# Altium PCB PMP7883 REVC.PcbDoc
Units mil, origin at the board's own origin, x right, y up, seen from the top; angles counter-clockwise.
Board outline 2805 x 1860 mil, 2 copper layers (Top Layer, Bottom Layer), stack 62.6 mil thick; 71 components, 35 nets, 157 pads, 20 vias.
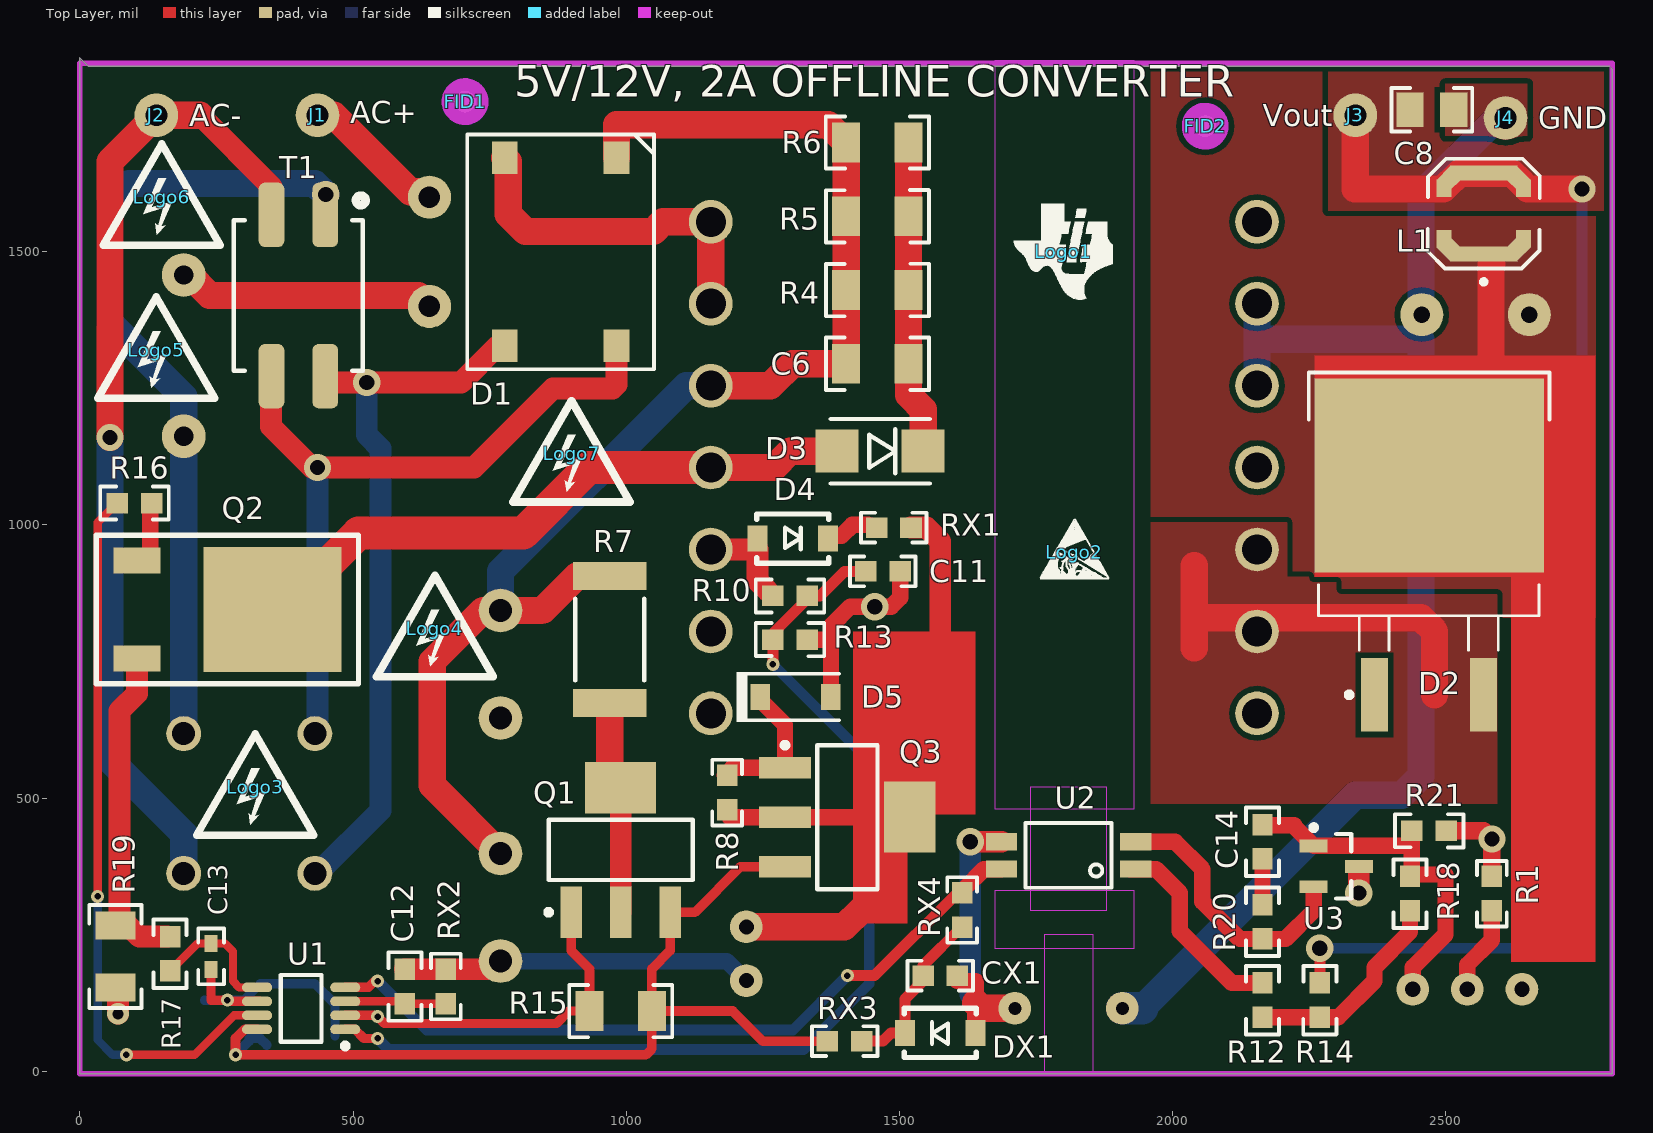
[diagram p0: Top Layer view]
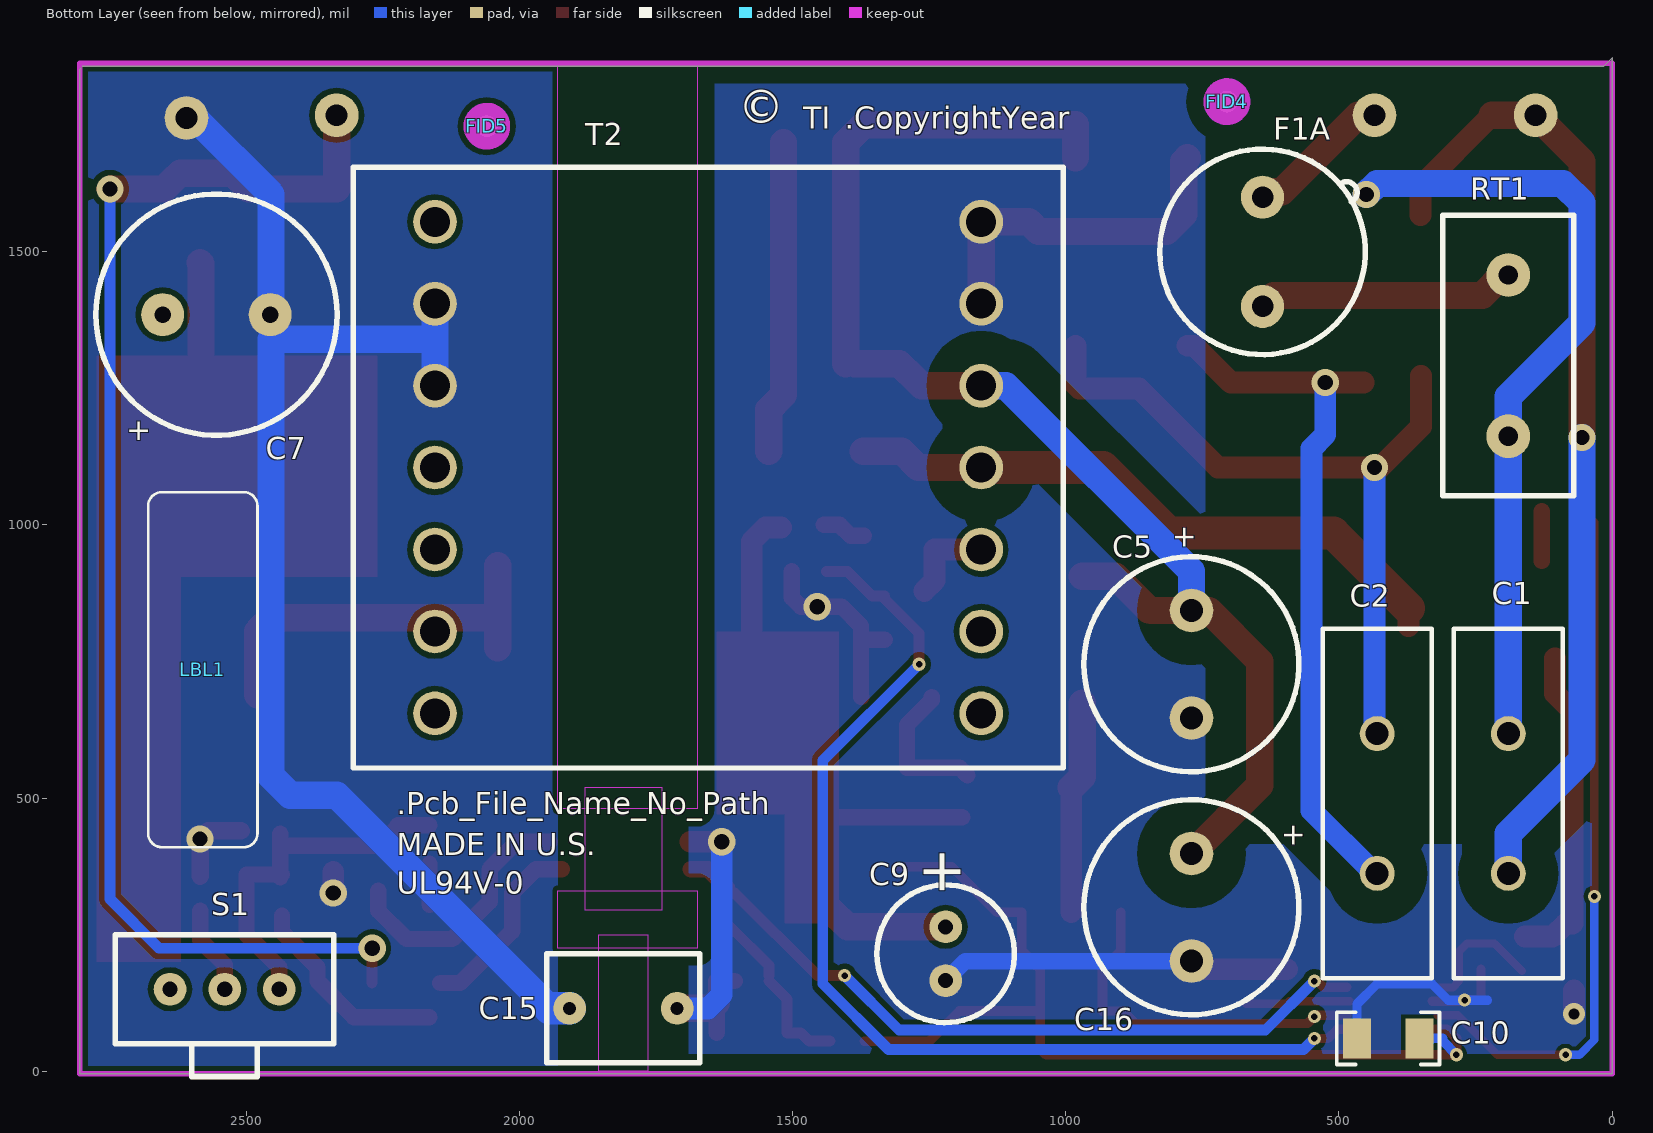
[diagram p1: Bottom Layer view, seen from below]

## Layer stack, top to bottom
Top Layer: signal copper 2.8
Dielectric: core 57, FR-4, Dk 4.8
Bottom Layer: signal copper 2.8

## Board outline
0,-5 2805,-5 2805,1835 2800,1840 15,1840 0,1855 0,-5

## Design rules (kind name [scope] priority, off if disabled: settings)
AcuteAngle [All] p1: minimum=4.50000000000000E+0001 checktracksonly=FALSE
AssemblyTestPointUsage [All] p1: valid=2
Clearance "Clearance T2_1_2" [(InPadClass('T2 Pin1_2')) vs InNet('GND')] p1: gap=10
Clearance "Clearance NetD4_2" [InNet('NetD4_2') vs InNet('GND')] p2: gap=10
Clearance "Clearance NetRX4_1" [InNet('NetRX4_1') vs InNet('GND')] p3: gap=10
Clearance "Clearance NetC11_1" [InNet('NetC11_1') vs InNet('GND')] p4: gap=10
Clearance "Clearance NetQ1_1" [InNet('NetQ1_1') vs InNet('GND')] p5: gap=10
Clearance Clearance_NetR16_1 [InNet('NetR16_1')] p6: gap=8
Clearance Clearance_NetC10_2 [InNet('NetC10_2')] p7: gap=8
Clearance Clearance_NetC9_1 [InNet('NetC9_1')] p8: gap=10
Clearance "Clearance VOUT" [InNet('VOUT')] p9: gap=10
Clearance "Clearance NetD2_3" [InNet('NetD2_3')] p10: gap=10
Clearance "Clearance SGND" [InNet('SGND')] p11: gap=10
Clearance Clearance_NetC7_1 [InNet('NetC7_1')] p12: gap=10
Clearance "Clearance_High Voltage to ALL" [(InNetClass('HIGH VOLTAGE'))] p13: gap=60
Clearance Clearance_Polygon [IsRegion] p14: gap=32
Clearance Clearance_BoardEdge_MountingHoles [OnCopper and InComponentClass('Mounting Holes') vs IsKeepOut] p15: gap=40
Clearance Clearance_BoardEdge_Poly [OnCopper and InPoly vs IsKeepOut] p16: gap=25
Clearance Clearance_BoardEdge [OnCopper and Not InComponentClass('Logo') and not InComponentClass('FiducialMark') and not InRegion(1000,500,4000,800) vs IsKeepOut] p17: gap=20
Clearance Clearance_IC [HasFootprint('MUA08A_L')] p18: gap=7
Clearance Clearance_All [All] p19: gap=8
ComponentClearance ComponentClearance_ScrewToNut [(HasFootprint('NY PMS 440 0025 PH')) vs (HasFootprint('Keystone_1902C'))] p1 off: gap=5 collisioncheckmode=3 verticalgap=10 showdistances=FALSE
ComponentClearance ComponentClearance_MountingHoles [InComponentClass('Mounting Holes')] p2 off: gap=40 collisioncheckmode=3 verticalgap=100000 showdistances=FALSE
ComponentClearance ComponentClearance_SmallPassives [HasFootprint('0201*') or HasFootprint('0402*') or HasFootprint('0508') or HasFootprint('0603*') or HasFootprint('0612') or HasFootprint('0805*') or HasFootprint('0815*') or HasFootprint('0830*') or HasFootprint('1206*') or HasFootprint('1210*') or HasFootprint('1808*') or HasFootprint('1812*') or HasFootprint('1825*') or HasFootprint('2010*') or HasFootprint('2220*') or HasFootprint('2225*') or HasFootprint('2512*') or HasFootprint('2728*') or HasFootprint('3518*') vs HasFootprint('0201*') or HasFootprint('0402*') or HasFootprint('0508') or HasFootprint('0603*') or HasFootprint('0612') or HasFootprint('0805*') or HasFootprint('0815*') or HasFootprint('0830*') or HasFootprint('1206*') or HasFootprint('1210*') or HasFootprint('1808*') or HasFootprint('1812*') or HasFootprint('1825*') or HasFootprint('2010*') or HasFootprint('2220*') or HasFootprint('2225*') or HasFootprint('2512*') or HasFootprint('2728*') or HasFootprint('3518*')] p3: gap=20 collisioncheckmode=3 verticalgap=10 showdistances=FALSE
ComponentClearance ComponentClearance_THtoSMT_TopLayer [IsThruComponent and OnLayer('Top Layer') vs IsSMTComponent and  OnLayer('Top Layer')] p4: gap=50 collisioncheckmode=3 verticalgap=100000 showdistances=FALSE
ComponentClearance ComponentClearance_THtoSMT_BotLayer [IsThruComponent and OnLayer('Bottom Layer') vs IsSMTComponent and  OnLayer('Bottom Layer')] p5: gap=50 collisioncheckmode=3 verticalgap=100000 showdistances=FALSE
ComponentClearance ComponentClearance_THtoTH [IsThruComponent vs IsThruComponent] p6: gap=50 collisioncheckmode=3 verticalgap=100000 showdistances=FALSE
ComponentClearance [All] p7: gap=50 collisioncheckmode=3 verticalgap=10 showdistances=FALSE
DiffPairsRouting [All] p1: maxlimit=100 minlimit=10 mostfreqgap=10 maxuncoupledlength=1000
FabricationTestPointUsage TestPointUsage [All] p1: valid=2 allowmultiple=FALSE
FabricationTestpoint Testpoint [All] p1: side=3 testpointundercomponent=TRUE minsize=40 maxsize=100 preferedsize=60 minholesize=0 maxholesize=40 preferedholesize=32 testpointgrid=1 allowsidetop=TRUE allowsidebottom=TRUE usegrid=TRUE gridtolerance=0.01
FanoutControl Fanout_LCC [IsLCC] p1: bgadir=Out bgaviamode=Centered fanoutstyle=Auto fanoutdirection=Alternating viagrid=1 // Fanout_LCC (Default Rule)
FanoutControl Fanout_BGA [IsBGA] p2: bgadir=Out bgaviamode=Centered fanoutstyle=Auto fanoutdirection=Alternating viagrid=1 // Fanout_BGA (Default Rule)
FanoutControl Fanout_Default [All] p4: bgadir=Out bgaviamode=Centered fanoutstyle=Auto fanoutdirection=Alternating viagrid=1 // Fanout_Default (Default Rule)
FanoutControl Fanout_Small [(CompPinCount < 5)] p5: bgadir=Out bgaviamode=Centered fanoutstyle=Auto fanoutdirection=OutThenIn viagrid=1 // Fanout_Small (Default Rule)
Height [All] p1 off: minheight=0 maxheight=1000 prefheight=500
HoleSize [All] p1: absolutevalues=TRUE maxlimit=251 minlimit=10 maxpercent=80.000 minpercent=20.000
MinimumAnnularRing [All] p1: minimumring=6
MinimumSolderMaskSliver MinimumSolderMaskSliver_Logo [InComponentClass('Logo') vs InComponentClass('Logo')] p1: minsoldermaskwidth=0.7
MinimumSolderMaskSliver [All] p2: minsoldermaskwidth=4
PlaneConnect [All] p1: planeconnectstyle=Relief reliefexpansion=10 reliefentries=4 reliefconductorwidth=10 reliefairgap=10
PolygonConnect [All] p1: connectstyle=Direct reliefconductorwidth=10 reliefentries=4 polygonreliefangle="90 Angle" airgapwidth=10
RoomDefinition "LM5023 APEC Rev 2" [InComponentClass('LM5023 APEC Rev 2')] p1 off: confinementstyle=ConfineIn formatcopy=TRUE lockcomponents=FALSE outline -692,-1534 1308,-1534 1308,-534 -692,-534
RoutingVias [All] p1: holewidth=16 width=34 viastyle="Through Hole" minholewidth=8 minwidth=26 maxholewidth=40 maxwidth=65
SMDToCorner [All] p1: distance=30000
SilkToSilkClearance [All] p1: silktosilkclearance=5
SilkscreenOverComponentPads [All] p1: minsilkscreentomaskgap=5
SolderMaskExpansion [All] p1: expansion=3
Width [All] p1: maxlimit=100 minlimit=6 preferedwidth=10 checkconnectedcopper=TRUE
13 further rules are at their usual default settings.

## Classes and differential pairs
component class "LM5023 APEC Rev 2": C1 C2 C5 C6 C7 C8 C9 C10 C11 C12 C13 C14 C15 C16 CX1 D1 D2 D3 D4 D5 DX1 F1 F1A J1 J2 J3 J4 L1 Q1 Q2 Q3 R1 R4 R5 R6 R7 R8 R10 R12 R13 R14 R15 R16 R17 R18 R19 R20 R21 RT1 RX1 RX2 RX3 RX4 S1 T1 T2 U1 U2 U3
component class FiducialMark: FID1 FID2 FID4 FID5
component class Logo: Logo1
net class "HIGH VOLTAGE": IN+ IN- NetC1_1 NetC2_1 NetC2_2 NetD3_2 NetF1A_1 VIN
component class Hardware_ANSI-B: !PCB FID1 FID2 FID4 FID5 LBL1 Logo1 Logo2 Logo3 Logo4 Logo5 Logo6 Logo7
component class Label: LBL1
pad class "T2 Pin1_2": T2-1 T2-2

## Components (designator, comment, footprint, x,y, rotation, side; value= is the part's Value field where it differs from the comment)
C1 "BC2361-ND" VY2103M63Y5US63V7 190,490 r270 bottom locked
C2 "BC2361-ND" VY2103M63Y5US63V7 430,490 r90 bottom locked
C5 "EEU-EE2W100U" EEUEE2W100U 770,745 r270 bottom
C6 "C3216C0G2J332J" 1206 1460,1295 r0 top
C7 "UHM1C152MPD" "10 X 20 HM" 2555,1385 r180 bottom
C8 "0805YD106MAT2A" 0805_HV 2475,1760 r0 top
C9 "ECA-2AM220" "PANASONIC M" 1220,215 r270 bottom
C10 "C3216X7R1E475K" 1206 410,60 r180 bottom
C11 "06035A471JAT2A" 0603 1470,915 r0 top
C12 "C1608C0G1E103J" 0603 595,155 r90 top
C13 "GRM1555C1H221JA01D" 0402 240,210 r270 top
C14 "C0603C821K5RACTU" 0603 2165,420 r270 top
C15 "DEBB33A221KC1B" "MURATA C1" 1810,115 r180 bottom
C16 "EEU-EE2W100U" EEUEE2W100U 770,300 r270 bottom
CX1 "0603YC104JAT2A" 0603 1575,175 r0 top
D1 "DF1506S" DF-S 880,1500 r270 top
D2 "8TQ100SPBF" DDPAK 2470,935 r90 top
D3 "US1J-13-F" SMA 1465,1135 r180 top
D4 "RF071M2S" SOD-123 1305,975 r180 top
D5 "MMSZ5245B-7-F" SOD-123 1310,685 r0 top
DX1 "MMSZ5229B-7-F" SOD-123 1575,70 r0 top
F1 "37002500410" 37002500410 3033,236 r0 top
F1A "56000001009" 56000001009 640,1500 r90 bottom
FID1 "Fiducial" Fiducial10-20 705,1775 r0 top
FID2 "Fiducial" Fiducial10-20 2060,1730 r0 top
FID4 "Fiducial" Fiducial10-20 705,1775 r180 bottom
FID5 "Fiducial" Fiducial10-20 2060,1730 r180 bottom
J1 "TH PAD" "TH PAD" 435,1750 r0 top
J2 "TH PAD" "TH PAD" 140,1750 r0 top
J3 "TH PAD" "TH PAD" 2335,1750 r0 top
J4 "TH PAD" "TH PAD" 2610,1745 r0 top
L1 "LPS4012-681MLB" LPS4012 2570,1570 r90 top
LBL1 "Size: 0.65\" x 0.20 \"" Label_650x200 2580,735 r270 bottom
Logo1 "Texas Instruments" TI_Symbol_Overlay_Small 1800,1500 r0 top
Logo2 "ESD Susceptible" ESD_Overlay_Small 1820,950 r0 top
Logo3 "DANGER HIGH VOLTAGE" IEC_HighVoltage_Small 321,520 r0 top
Logo4 "DANGER HIGH VOLTAGE" IEC_HighVoltage_Small 650,810 r0 top
Logo5 "DANGER HIGH VOLTAGE" IEC_HighVoltage_Small 140,1320 r0 top
Logo6 "DANGER HIGH VOLTAGE" IEC_HighVoltage_Small 150,1600 r0 top
Logo7 "DANGER HIGH VOLTAGE" IEC_HighVoltage_Small 900,1130 r0 top
Q1 "BSP135 L6433" SOT-223 990,405 r90 top
Q2 "IPD60R750E6" "PG TO252-3" 270,845 r180 top
Q3 "PZTA42,115" SOT-223 1405,465 r0 top
R1 "CRCW060311K0FKEA" 0603 2585,325 r270 top
R4 "CRCW1206249KFKEA" 1206 1460,1430 r0 top
R5 "CRCW1206249KFKEA" 1206 1460,1565 r180 top
R6 "CRCW1206249KFKEA" 1206 1460,1700 r0 top
R7 "10k" 2512 970,790 r90 top
R8 "RC0603FR-0723K7L" 0603 1185,510 r270 top
R10 "CRCW060363K4FKEA" 0603 1300,870 r180 top
R12 "CRCW06031K21FKEA" 0603 2165,130 r270 top
R13 "CRCW06032K80FKEA" 0603 1300,790 r180 top
R14 "CRCW060310R0FKEA" 0603 2270,130 r90 top
R15 "CRCW120610M0FKEA" 1206 990,110 r0 top
R16 "CRCW06034R75FKEA" 0603 100,1040 r0 top
R17 "CRCW06031K00FKEA" 0603 165,215 r90 top
R18 "CRCW060360K4FKEA" 0603 2435,325 r270 top
R19 "CSR1206FKR250" 1206 65,210 r90 top
R20 "CRCW0603604KFKEA" 0603 2165,273.5 r90 top
R21 "CRCW060320K0FKEA" 0603 2470,440 r180 top
RT1 "MF72-030D11" MF72-D11_02 190,1310 r270 bottom
RX1 "RC0603FR-0722R1L" 0603 1490,995 r180 top
RX2 "RC0603FR-07100KL" 0603 670,155 r270 top
RX3 "CRCW06031K00FKEA" 0603 1400,55 r180 top
RX4 "CRCW06031K00FKEA" 0603 1615,295 r270 top
S1 "SS12SDH2" SS12SDH2 2540,150 r180 bottom
T1 "50475C" 50475C 400,1420 r270 top
T2 "custom" 7508112324_0 1655,1105 r0 bottom locked
U1 "LM5023" MUA08A_L 405,115 r180 top
U2 "PS2811-1-M-A" PS2811-1 1810,395 r180 top
U3 "LMV431BIMF/NOPB" MF03A_N 2300,375 r0 top

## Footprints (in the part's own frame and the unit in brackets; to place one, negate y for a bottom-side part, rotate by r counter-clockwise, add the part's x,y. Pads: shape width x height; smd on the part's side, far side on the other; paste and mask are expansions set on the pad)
"10 X 20 HM" [mm] "10 X 20 RADIAL NICHICON HM"
  round 2 hole 0.762: 1(-2.5,0) 2(2.5,0)
  silkscreen extent -5.61,-5.61 5.61,5.61, body extent -5.59,-5.59 5.59,5.59, height 20
0402 [mm] "0402 from SM-752 data"
  rect 0.8x0.6 smd: 1(-0.6,0) 2(0.6,0)
  silkscreen extent -1.3,-0.6 1.3,0.6, body extent -0.55,-0.3 0.55,0.3, height 0.6
0603 [mm] "0603 from SM-752 data"
  rect 1x0.95 smd: 1(-0.8,0) 2(0.8,0)
  silkscreen extent -1.52,-0.69 1.52,0.69, body extent -0.87,-0.47 0.87,0.47, height 0.85
0805_HV [mil] "0805 with 30mil clearance between pads"
  rect 50x63 smd: 1(-40,0) 2(40,0)
  silkscreen extent -74,-40 74,40, body extent -43,-29 43,29, height 43
1206 [mm] "1206 from SM-752 data"
  rect 1.3x1.85 smd: 1(-1.45,0) 2(1.45,0)
  silkscreen extent -2.39,-1.22 2.39,1.22, body extent -1.7,-0.9 1.7,0.9, height 1.35
2512 [mm] "Chip Resistor, Body 6.3x3.2mm, IPC Medium Density"
  rect 1.3x3.4 smd: 1(-2.95,0) 2(2.95,0)
  silkscreen extent -1.9,-1.6 1.9,1.6, body extent -3.22,-1.67 3.22,1.67, height 0.71
50475C [mm] "CHOKE COMMON MODE 4.7MH 0.4A SMD"
  rrect50% 3x1.2 smd: 1(-3.75,1.25) 2(-3.75,-1.25) 3(3.75,-1.25) 4(3.75,1.25)
  silkscreen extent -4.65,-3 3.5,3.12, body extent -3.5,-3 3.5,3, height 3.8
7508112324_0 [mil] "Wurth Elektronik Transformer"
  round 60 on Bottom Overlay: 0(-700,550)
  round 80 hole 55: 1(-500,450) 2(-500,300) 3(-500,150) 4(-500,0) 5(-500,-150) 6(-500,-300) 7(-500,-450) 8(500,-450) 9(500,-300) 10(500,-150) 11(500,0) 12(500,150) 13(500,300) 14(500,450)
  silkscreen extent -650,-550 650,550, body extent -650,-550 650,550, height 900
37002500410 [mil] "FUSE FAST 250VAC 250MA RADIAL"
  body extent -166,-167 167,167, height 484
56000001009 [mm] "Fuseholders, Clips, & Hardware 6.3A/1.6W/4.3mm TR5/TE5 Holder"
  round 2 hole 1: 1(-2.54,0) 2(2.54,0)
  silkscreen extent -4.78,-4.78 4.78,4.78, body extent -4.75,-4.72 4.71,4.76, height 5.7
DDPAK [mil] "D2-PAK, 3-Pads, Body 9.7x10.4mm (max), TO-263AB, using Vishay Silionix recommended pad sizes"
  rect 135x49.49 smd: 1(-246.06,100) 3(-246.06,-100)
  rect 355x420 smd paste-181.1: 4(155.51,0)
  silkscreen extent -251,-220 344,220, body extent -295,-202 324,202, height 180
DF-S [mm] "Diodes Inc. recommended land pattern per ap02001.pdf rev 30"
  rect 1.52x1.2 smd: 1(-4.37,2.6) 2(-4.37,-2.6) 3(4.37,-2.6) 4(4.37,2.6)
  silkscreen extent -5.46,-4.34 5.46,4.34, body extent -3.34,-4.36 3.34,4.33, height 2.6
EEUEE2W100U [mil] "CAP ALUM 10UF 450V 20% RADIAL"
  round 80 hole 42: 1(-98.43,0) 2(98.43,0)
  silkscreen extent -197,-197 197,197, body extent -195,-196 200,196, height 799
ESD_Overlay_Small [mil]
  silkscreen extent -62,-48 64,61
Fiducial10-20 [mm]
  round 1 smd paste-0.5 mask+0.5: 1(0,0)
  Keep-Out Layer circle w1.178: c0,0 r0.5
IEC_HighVoltage_Small [mil]
  silkscreen extent -107,-88 107,97
Label_650x200 [mil] "Thermal Transfer Label"
  silkscreen extent -325,-100 325,100, body extent -326,-101 326,101, height 1
LPS4012 [mm] "Coilcraft recommended land pattern.  Document 433-2, rev 10/20/08"
  rect 0.7x3.124 smd: 1(-1.881,0) 2(1.881,0)
  rect 0.902x0.801 smd rot 45: 1(-1.592,1.605) 2(1.592,-1.605)
  rect 0.902x0.801 smd rot 135: 1(-1.592,-1.605) 2(1.592,1.605)
  rect 0.812x0.7 smd: 1(-1.168,1.85) 1(-1.168,-1.85) 2(1.168,1.85) 2(1.168,-1.85)
  silkscreen extent -3.26,-2.6 2.55,2.6, body extent -2.05,-2.05 2.05,2.05, height 1.22
MF03A_N [mm] "SOT23, 3-Leads, Body 2.9x1.3mm, Pitch 0.95mm, Lead Span 2.4mm, IPC Medium Density"
  rect 1.3x0.6 smd: 1(-1.05,0.95) 2(-1.05,-0.95) 3(1.05,0)
  silkscreen extent -1.17,-1.5 0.7,1.92, body extent -0.7,-1.5 0.7,1.5, height 1.12
MF72-D11_02 [mil] "Cantherm Current Limiter MF72-D11_02 Type"
  round 80 hole 35: 1(-147.64,0) 2(147.64,0)
  silkscreen extent -257,-120 257,120, body extent -260,-120 260,120, height 520
MUA08A_L [mm] "TSOP, 8-Leads, Body 3x3mm, Pitch 0.65mm, IPC High Density"
  oval 1.4x0.45 smd: 1(-2.05,0.975) 2(-2.05,0.325) 3(-2.05,-0.325) 4(-2.05,-0.975) 5(2.05,-0.975) 6(2.05,-0.325) 7(2.05,0.325) 8(2.05,0.975)
  silkscreen extent -2.17,-1.55 0.95,1.87, body extent -1.6,-1.6 1.6,1.6, height 1.09
"MURATA C1" [mil] "MURATA DEBB C1"
  round 60 hole 23.62: 1(-98.43,0) 2(98.43,0)
  silkscreen extent -140,-100 140,100, body extent -140,-100 140,100, height 591
"PANASONIC M" [mil] "PANASONIC M TYPE ALUMINUM CAPACITOR"
  round 60 hole 27.56: 1(-49.21,0) 2(49.21,0)
  silkscreen extent -126,-126 126,126, body extent -125,-125 125,125, height 441
"PG TO252-3" [mm] "TO252-3 INFINEON TECHNOLOGIES"
  rect 2.2x1.2 smd: 1(4.2,-2.28) 3(4.2,2.28)
  rect 6.4x5.8 smd: 2(-2.1,0)
  silkscreen extent -6.1,-3.45 6.1,3.45, body extent -6.07,-3.5 6.07,3.47, height 2.41
PS2811-1 [mm] "NEC optocoupler"
  rect 1.45x0.8 smd: 1(-3.125,0.635) 2(-3.125,-0.635) 3(3.125,-0.635) 4(3.125,0.635)
  silkscreen extent -2,-1.5 2,1.5, body extent -2.2,-1.5 2.2,1.5, height 2.1
SMA [mm] "Molded Diode, 2-Leads, Body 4.3x2.6mm, IPC Medium Density, based on OnSemi component dimensions and land pattern"
  rect 2x2 smd: 1(-2,0) 2(2,0)
  silkscreen extent -2.3,-1.5 2.3,1.5, body extent -2.28,-1.46 2.29,1.46, height 2.27
SOD-123 [mm] "On Semi recommended land pattern"
  rect 0.915x1.22 smd: 1(-1.637,0) 2(1.637,0)
  silkscreen extent -1.68,-1.14 1.68,1.14, body extent -1.42,-0.9 1.42,0.9, height 1.35
SOT-223 [mm] "SOT223/SC73, 4-Leads, Body 6.5x3.5mm, Pitch 2.3mm, Lead Span 7mm, IPC Medium Density"
  rect 2.4x1 smd: 1(-2.9,2.3) 2(-2.9,0) 3(-2.9,-2.3)
  rect 2.4x3.3 smd: 4(2.9,0)
  silkscreen extent -3.02,-3.35 1.4,3.47, body extent -1.85,-3.35 1.85,3.35, height 1.8
SS12SDH2 [mil] "NKK SERIES SS SWITCH"
  round 60 hole 28: 1(-100,0) 2(0,0) 3(100,0)
  silkscreen extent -200,-160 200,100, body extent -200,-160 200,100, height 150
"TH PAD" [mil] "THROUGH HOLE PAD"
  round 80 hole 40: 1(0,0)
TI_Symbol_Overlay_Small [mil]
  silkscreen extent -90,-88 91,88
VY2103M63Y5US63V7 [mil] "CAP CER 10000PF 300V 20% RADIAL"
  round 64 hole 42: 1(-127.95,0) 2(127.95,0)
  silkscreen extent -320,-100 320,100, body extent -314,-99 314,98, height 785

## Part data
C1 C2: library part VY2103M63Y5US63V7, "CAP CER 10000PF 300V 20% RADIAL"
C5 C16: library part EEUEE2W100U, "CAP ALUM 10UF 450V 20% RADIAL"
C6: "CAP, CERM, 3300pF, 630V, +/-5%, C0G/NP0, 1206"
C7: library part Capacitor_Polarized, "CAP, [CAP ALUM 1500UF 16V 20% RADIAL"
C8: "CAP, CERM, 10uF, 16V, +/-20%, X5R, 0805"
C9: "CAP ALUM 22UF 100V 20% RADIAL"
C10: "CAP, CERM, 4.7uF, 25V, +/-10%, X7R, 1206"
C11: "CAP, CERM, 470pF, 50V, +/-5%, C0G/NP0, 0603"
C12: "CAP, CERM, 0.01uF, 25V, +/-5%, C0G/NP0, 0603"
C13: "CAP, CERM, 220pF, 50V, +/-5%, C0G/NP0, 0402"
C14: "CAP, CERM, 820pF, 50V, +/-10%, X7R, 0603"
C15: "CAP CER 220PF 1KV 10% RADIAL"
CX1: "CAP, CERM, 0.1uF, 16V, +/-5%, X7R, 0603"
D1: "Diode, Switching-Bridge, 600V, 1.5A, DF-S"
D2: "DIODE SCHOTTKY 100V 8A D2PAK"
D3: library part SS14-E3/61T, "Diode, Schottky, 600V, 1A, SMA"
D4: "Diode, Ultrafast, 200V, 1A, SOD-123"
D5: "Diode, Zener, 15V, 500mW, SOD-123"
DX1: "Diode, Zener, 4.3V, 500mW, SOD-123"
F1: "FUSE FAST 250VAC 250MA RADIAL"
F1A: "Fuseholders, Clips, & Hardware 6.3A/1.6W/4.3mm TR5/TE5 Holder"
FID1 FID2 FID4 FID5: "Fiducial mark.  There is nothing to buy or mount."
J1 J2 J3 J4: "THROUGH HOLE PAD"
L1: "Inductor, Shielded Drum Core, Ferrite, 680nH, 2.4A, 0.05 ohm, SMD"
LBL1: library part THT-14-423-10, "Thermal Transfer Printable Labels, 0.650\" W x 0.200\" H - 10,000 per roll"
Logo1: library part TI_Logo, "Texas Instrument Corporate Signature"
Logo2: library part ESD_Susceptible, "ESD Susceptible Symbol"
Logo3 Logo4 Logo5 Logo6 Logo7: library part IEC_HighVoltage, "IEC 61010-1 High Voltage Warning"
Q1: library part BSP135, "MOSFET N-CH 600V 120MA SOT-223"
Q2: "MOSFET N-CH 600V 5.7A TO252-3"
Q3: library part PZTA42, "TRANS NPN 300V 100MA SOT223"
R1: "RES, 11.0k ohm, 1%, 0.1W, 0603"
R4 R5 R6: "RES, 249k ohm, 1%, 0.25W, 1206"
R7: library part CRCW251210K0FKEGHP, "RES 10.0K OHM 1W 1% 2512 SMD"
R8: library part Resistor, "RES 23.7K OHM 1/10W 1% 0603 SMD"
R10: "RES, 63.4k ohm, 1%, 0.1W, 0603"
R12: "RES, 1.21k ohm, 1%, 0.1W, 0603"
R13: "RES, 2.80k ohm, 1%, 0.1W, 0603"
R14: "RES, 10.0 ohm, 1%, 0.1W, 0603"
R15: "RES, 10.0Meg ohm, 1%, 0.25W, 1206"
R16: "RES, 4.75 ohm, 1%, 0.1W, 0603"
R17 RX3 RX4: "RES, 1.00k ohm, 1%, 0.1W, 0603"
R18: "RES, 60.4k ohm, 1%, 0.1W, 0603"
R19: "RES, 0.25 ohm, 1%, 0.5W, 1206"
R20: "RES, 604k ohm, 1%, 0.1W, 0603"
R21: "RES, 20.0k ohm, 1%, 0.1W, 0603"
RT1: "CURRENT LIMITER INRUSH 30OHM 20%"
RX1: "RES, 22.1 ohm, 1%, 0.1W, 0603"
RX2: "RES, 100k ohm, 1%, 0.1W, 0603"
S1: "SW SLIDE ULTR MINI SPDT SIDE ACT"
T1: "CHOKE COMMON MODE 4.7MH 0.4A SMD"
T2: library part 7508112324_0, "Werth Elektronik Transformer"
U1: "IC, CTLR, AC-DC Quasi Resonant PWM"
U2: "Low Input Current, Hight CTR Photocoupler"
U3: library part LMV431BIMF, "IC VREF SHUNT PREC ADJ SOT-23-3"

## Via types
v1: diameter 50, hole 28, Top Layer to Bottom Layer, 10 vias
v2: diameter 24, hole 12, Top Layer to Bottom Layer, 9 vias
v3: diameter 40, hole 20, Top Layer to Bottom Layer, 1 vias

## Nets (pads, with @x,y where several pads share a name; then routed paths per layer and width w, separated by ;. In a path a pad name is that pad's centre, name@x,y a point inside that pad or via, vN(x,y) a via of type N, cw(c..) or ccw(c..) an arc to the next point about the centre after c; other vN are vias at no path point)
GND: C5.2 C9.2 C10.1 C11.2 C12.2 C13.2 C15.2 C16.2 CX1.2 D1.2 D5.2 DX1.2 R13.1 R19.1 RX2.1 T2.6 T2.7 U1.6 U2.3 | length 2777.2
  Top Layer w17: C13.2 240,130 v2(270,130) ; v2@272.2,127.8 U1.6@329.29,127.8
  Top Layer w30: R13.1 1375,790 ; D5.2 1375,685.53 1375,790 ; C11.2 1501.5,866.5 1485,850 1410,850 1375,815 1375,790 ; CX1.2@1606.5,165 1640,165 1640,125 ; DX1.2 1639.47,119.47
  Top Layer w40: v3(70,105) R19.1@70,147.91 ; C12.2 744.92,186.5 C16.2@760,201.57 ; v1(1630,420) U2.3
  Top Layer w50: D1.2 784.37,1665.31 784.37,1568.63 815.87,1537.13 1049.48,1537.13 1067.35,1555 T2.7@1130,1555 ; T2.6 T2.7 ; 1640,125 1650,115 C15.2
  Bottom Layer w17: 228,130 v2(270,130) 300,130 330,160 430,160 467.09,122.91 C10.1@467.09,65
  Bottom Layer w30: C16.2@760,201.57 1184.21,201.57 C9.2
  Bottom Layer w40: v1(1630,420) 1630,140 1655,115 C15.2
  other v1: 1455,850
IN+: F1A.2 J1.1 | length 263
  Top Layer w50: J1.1 465,1750 605,1610 F1A.2@640,1610
IN-: C1.2 J2.1 T1.2 | length 1790.6
  Top Layer w40: 220,1750 350.79,1619.21 T1.2
  Top Layer w50: v1(55,1160) 55,1555 ; 55,1560 55,1665 J2.1 220,1750
  Bottom Layer w50: v1(55,1160) 55,570 190,435 C1.2
NetC1_1: C1.1 RT1.2 T1.1 | length 1445.7
  Bottom Layer w50: C1.1 RT1.2 190,1235 55,1370 55,1590 90,1625 430,1625 v1(450,1605)
NetC2_1: C2.1 D1.3 T1.4 | length 1307.6
  Top Layer w40: T1.4@454.52,1260.63 697.73,1260.63 765.05,1327.95 D1.3
  Bottom Layer w40: C2.1@435,362.05 550,477.05 550,1140 525,1165 v1(525,1260.63)
NetC2_2: C2.2 D1.4 T1.3 | length 1376.5
  Top Layer w40: T1.3@350,1272.36 350,1180 425,1105 721.37,1105 866.37,1250 975,1250 982.36,1257.36 D1.4
  Bottom Layer w40: C2.2@435,617.95 v1(435,1105)
NetC6_2: C6.2 D3.1 R4.2 R5.1 R6.2 | length 576
  Top Layer w50: R6.2 R5.1 R4.2 C6.2 1517.09,1237.91 1543.74,1211.26 D3.1
NetC7_1: C7.1 D2.4 L1.1 | length 265.4
  Top Layer w50: 2585,1480 2583.43,1478.43 2583.43,1385 2583.43,1231.57 D2.4@2595,1220
NetC9_1: C9.1 Q3.2 Q3.4 R8.2 RX1.1 | length 875.1
  Top Layer w30: R8.2@1190,465 1444.17,465 1521.5,542.32
  Top Layer w40: RX1.1 1550,995 1575,970 1575,745
  Top Layer w50: C9.1 1399.21,264.21 1430,295
NetC10_2: C10.2 Q1.3 Q3.3 R15.2 RX3.2 U1.8 | length 1792.8
  Top Layer w17.72: U1.8 301.61,76.61 285,60 v2(285,30) 1036.14,30 1047.09,40.94 R15.2 ; Q3.3@1310.55,374.45 Q3.3 1209.45,374.45 1125.83,290.83 Q1.3 1080.55,220.55 1047.09,187.09 R15.2 ; RX3.2 1250,55 1195,110 R15.2
  Bottom Layer w17.72: v2(285,30) 310,55 310,60 330,60 C10.2@342.09,47.91
NetC11_1: C11.1 R10.1 R13.2 U1.1 | length 1957.5
  Top Layer w17: U1.1 503.39,76.61 520,60 v2(545,60)
  Top Layer w20: v2@1268.5,746.5 R13.2 1268.5,801.39 1331.5,864.39 R10.1 1355,870 1400,915 C11.1
  Bottom Layer w20: v2(545,60) 565,40 1325,40 1445,160 1445,568.5 v2(1268.5,745)
NetC12_1: C12.1 RX2.2 U1.3 | length 191.2
  Top Layer w16: U1.3@480.71,127.8 U1.3 485.91,128 551.6,128 551.8,127.8 590.71,127.8 C12.1 RX2.2
NetC13_1: C13.1 R17.1 U1.5 | length 245.1
  Top Layer w15: R17.1 215.12,233.62 C13.1 265.69,233.62 280,219.31 280,165 291.61,153.39 U1.5
NetC14_1: C14.1 R18.1 R21.2 S1.3 U3.1 | length 670.1
  Top Layer w30: C14.1@2165,450 2223.03,450 2223.03,448.03 U3.1 2438.5,412.4 ; R18.1@2435,360 2500,360 2500,250 2440,190 S1.3 ; R18.1@2438.5,355 R21.2@2438.5,435
NetC14_2: C14.2 R20.2 | length 75
  Top Layer w30: R20.2 C14.2@2165,380
NetCX1_1: CX1.1 DX1.1 RX3.1 RX4.2 | length 312.9
  Top Layer w20: RX3.1 1470,55 1485,70 DX1.1 1510.53,132.03 CX1.1@1543.5,165 ; CX1.1 1543.5,193.5 1613.5,263.5 RX4.2
NetD2_3: D2.3 T2.12 T2.13 | length 716.4
  Top Layer w50: 2040,775 2040,830 ; 2040,925 2040,830 ; 2480,688.94 2480,805 2455,830 2040,830
NetD3_2: D3.2 Q2.2 T2.4 | length 1125.3
  Top Layer w40: Q2.2@372.68,815 Q2.2@372.68,847.68
  Top Layer w50: T2.4 1270,1105 1300,1135 D3.2@1371.26,1135
  Top Layer w60: Q2.2@372.68,847.68 510,985 811.78,985 931.78,1105 T2.4@1130,1105
NetD4_1: D4.1 RX1.2 | length 82.3
  Top Layer w30: D4.1@1369.47,980 1394.22,980 1414.22,1000 RX1.2@1443.5,1000
NetD4_2: D4.2 R10.2 T2.3 | length 169
  Top Layer w40: T2.3 1240.53,955 1240.53,897.97 R10.2@1259.25,879.25
NetD5_1: D5.1 Q3.1 R8.1 | length 264.9
  Top Layer w30: R8.1@1180,541.5 1194.06,555.55 Q3.1 1290.83,634.17 1245.53,679.47 D5.1
NetF1A_1: F1A.1 RT1.1 | length 463.9
  Top Layer w50: RT1.1@200,1457.64 237.64,1420 620,1420 F1A.1
NetQ1_1: Q1.1 R15.1 U1.2 | length 649.3
  Top Layer w17: U1.2 v2@537.8,102.2 ; v2(545,100) 557.68,87.32 872.32,87.32 895,110 R15.1
  Top Layer w17.72: Q1.1 899.45,220.55 932.91,187.09 R15.1
NetQ1_2: Q1.2 Q1.4 R7.1 | length 391.3
  Top Layer w40: Q1.2 Q1.4
  Top Layer w50: R7.1 970,539.17 Q1.4
NetQ2_1: Q2.1 R16.2 | length 91
  Top Layer w30: Q2.1@128.5,934 R16.2@128.5,1025
NetQ2_3: Q2.3 R17.2 R19.2 | length 595.8
  Top Layer w40: Q2.3 104.65,691.65 72.5,659.5 72.5,270 85,270 108.5,246.5 R17.2@160,246.5
NetR1_2: R1.2 S1.2 | length 162.1
  Top Layer w30: S1.2 2540,195 2585,240 R1.2
NetR12_1: R12.1 U2.1 | length 349.3
  Top Layer w30: U2.1@1923.03,370 1970,370 2013.75,326.25 2013.75,256.25 2108.5,161.5 2145,161.5
NetR12_2: R12.2 R14.1 R18.2 | length 379.5
  Top Layer w30: R12.2 R14.1 2303.5,98.5 2370,165 2370,190 2435,255 R18.2@2435,285
NetR16_1: R16.1 U1.7 | length 1325.7
  Top Layer w15: v2(32.5,320) 32.5,1004.5 R16.1@68.25,1040.25 ; v2(85,30) 210,30 282.2,102.2 U1.7@319.29,102.2
  Bottom Layer w15: v2(32.5,320) 32.5,57.5 60,30 v2(85,30)
NetR20_1: R20.1 U2.2 U3.2 | length 480.3
  Top Layer w30: U2.2@1945,420 2005,420 2055,370 2055,310 2122.99,242.01 R20.1 2207.01,242.01 2258.66,293.66 U3.2@2258.66,330
NetRX4_1: RX4.1 U1.4 U2.4 | length 1343.5
  Top Layer w17: U1.4 528.39,153.39 v2@540,165
  Top Layer w20: v2(1405,175) 1455,175 RX4.1@1606.5,326.5
  Top Layer w30: RX4.1@1620,335 1655,370 U2.4
  Bottom Layer w20: v2(545,165) 635,75 1305,75 v2(1405,175)
SGND: C7.2 C8.2 C15.1 J4.1 R1.1 R21.1 T2.9 T2.10 U3.3 | length 2594
  Top Layer w32: R21.1@2510,440 2570,440 v1(2585,425) R1.1
  Top Layer w40: v1(2341.34,326.34) U3.3@2341.34,365
  Bottom Layer w50: 1945,115 2335,505 2420,505 2455,540 2455,1340 2155,1340 ; T2.10 2155,1340 ; T2.9 2155,1340 ; C7.2@2455,1385 2455,1605 2595,1745 J4.1
  Bottom Layer w60: C15.1 1945,115
VIN: C5.1 C6.1 C16.1 D1.1 R4.1 R5.2 R6.1 R7.2 T2.5 | length 2521.4
  Top Layer w50: C16.1 645,523.43 645,750 738.43,843.43 C5.1 843.43,843.43 845,845 848.55,845 909.69,906.14 R7.2 ; D1.1 982.36,1732.64 1370.28,1732.64 R6.1 R5.2 R4.1 C6.1 ; T2.5 1264.03,1255 1288.4,1279.37 1289.37,1279.37 1305,1295 C6.1@1386.5,1295
  Bottom Layer w50: C5.1@778.21,843.43 C5.1 770,915 1110,1255 T2.5@1130,1255
VOUT: C8.1 J3.1 L1.2 R14.2 | length 2454.9
  Top Layer w20: R14.2 v1(2270,225)
  Top Layer w50: J3.1 2335,1615 2496.17,1615 2497.17,1616 2525.22,1644.06 2570,1644.06 2621.79,1644.06 2633.18,1632.67 2650.84,1615 v1(2750,1615)
  Bottom Layer w20: v1(2270,225) 2660,225 2750,315 v1(2750,1615)
pads on no net: D2.1 FID1.1 FID2.1 FID4.1 FID5.1 S1.1 T2.0 T2.1 T2.2 T2.8 T2.11 T2.14

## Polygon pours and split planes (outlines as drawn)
SGND on Bottom Layer "Bottom Layer-SGND " (solid, remove dead copper, pour order 9): 2805,1845 1930,1845 1930,-5 2805,-5
GND on Bottom Layer "Bottom Layer-GND" (solid, remove dead copper, pour order 14): 745,1845 1690,1845 1690,-10 745,-10 0,-5 0,985 160,985 165,415 745,415
SGND on Top Layer "Top Layer-SGND" (solid, remove dead copper, pour order 13): 2650,1845 2650,1700 2500,1700 2500,1845
NetD2_3 on Top Layer "Top Layer-NetD2_3" (solid, pour order 11): 1960,1005 1960,490 2595,490 2595,905 2210,905 2210,1005
VOUT on Top Layer "Top Layer-VOUT" (solid, remove dead copper, pour order 15): 2805,1575 2805,1845 2285,1845 2285,1575
NetC7_1 on Top Layer "Top Layer-Net C7_1" (solid, remove dead copper, pour order 12): 1960,1005 2220,1005 2220,830 2775,830 2775,1565 2280,1565 2280,1845 1960,1845

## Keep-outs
Keep-Out Layer:
  rectangle: 1765,0 1855,250
  rectangle: 1740,295 1880,520
  rectangle: 1675,225 1930,330
  rectangle: 1675,480 1930,1850
  lines w10: 0,-5 2805,-5 2805,1845 0,1845 0,0
  text ".Layer_Name" at 577,-858.49 h40
  text "880" at 3117.5,-858.49 h40

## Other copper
Top Layer:
  rectangle net NetC9_1: 1415,270 1515,470
  rectangle net NetC9_1: 1415,470 1640,805
  rectangle net NetC7_1: 2260,905 2775,1310
  rectangle net NetC7_1: 2620,200 2775,940
  text ".Layer_Name" at 577,-858.49 h40
  text "880" at 3117.5,-858.49 h40
Bottom Layer:
  text ".Layer_Name" at 577,-858.49 h40
  text "880" at 3117.5,-858.49 h40

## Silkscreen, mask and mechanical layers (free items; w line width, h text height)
Top Overlay:
  text "5V/12V, 2A OFFLINE CONVERTER" at 795,1765 h100
  text "AC+" at 495,1735 h40
  text "AC-" at 200,1730 h40
  text "Vout" at 2165,1730 h40
  text "GND" at 2670,1725 h40
  text ".Layer_Name" at 577,-858.49 h40
  text "880" at 3117.5,-858.49 h40
Bottom Overlay:
  text ".CopyrightYear" at 1405,1725 h40
  text "TI" at 1481,1725 h40
  text "©" at 1600,1715 h105
  text ".Pcb_File_Name_No_Path" at 2225,470 h40
  text "MADE IN U.S." at 2225,395 h40
  text "UL94V-0" at 2225,325 h40
  text ".Layer_Name" at 577,-858.49 h40
  text "880" at 3117.5,-858.49 h40
Top Paste:
  text ".Layer_Name" at 577,-858.49 h40
  text "881" at 3117.5,-858.49 h40
Bottom Paste:
  text ".Layer_Name" at 577,-858.49 h40
  text "881" at 3117.5,-858.49 h40
Top Solder:
  text "TI" at 870,70 h40
  text ".Layer_Name" at 577,-858.49 h40
  text ".Layer_Name" at 577,-858.49 h40
  text "880" at 3117.5,-858.49 h40
Bottom Solder:
  text ".Layer_Name" at 577,-858.49 h40
  text "880" at 3117.5,-858.49 h40
Drill Guide:
  text ".Layer_Name" at 577,-858.49 h40
  text "880" at 3117.5,-858.49 h40
M1 Board Outline:
  lines w5: 0,0 0,1840 2800,1840 2800,0 0,0
  text ".Layer_Name" at 577,-858.49 h40
  text "880" at 3117.5,-858.49 h40
M2 Board Dimensions:
  rectangle: -0.5,-285.5 124.5,-160.5
  rectangle: 124.5,-410.5 499.5,-285.5
  lines w7: -0.5,-285.5 999.5,-285.5 ; 124.5,-410.5 124.5,-160.5 ; 249.5,-410.5 249.5,-160.5 ; 499.5,-410.5 499.5,-160.5 ; 749.5,-410.5 749.5,-160.5 ; -0.5,-410.5 999.5,-410.5 999.5,-160.5 -0.5,-160.5 -0.5,-410.5
  lines w10: -0.5,-475.5 -0.5,-455.5 ; 59.5,-485.5 -0.5,-465.5 ; 59.5,-445.5 -0.5,-465.5 ; 223.58,-465.5 -0.5,-465.5 ; 775.42,-465.5 999.5,-465.5 ; 939.5,-485.5 999.5,-465.5 ; 939.5,-445.5 999.5,-465.5 ; 999.5,-475.5 999.5,-455.5
  text "1000 (mil)" at 233.58,-501.49 h60
  text ".Layer_Name" at 577,-858.49 h40
  text "880" at 3117.5,-858.49 h40
M3 3D STEP Top:
  text ".Layer_Name" at 577,-858.49 h40
  text "880" at 3117.5,-858.49 h40
M4 3D STEP Bottom:
  text ".Layer_Name" at 577,-858.49 h40
  text "880" at 3117.5,-858.49 h40
M5 Assembly Top:
  lines w7: -292,-930.17 6308,-930.17 ; -292,-726.83 6310,-726.83 ; -292,-523.5 -292,-1133.5 3713,-1133.5 6310,-1133.5 6310,-523.5 -291.5,-523.5 -291.5,-1133.5 1284,-1133.5 ; 2173,-929 2173,-523.5 ; 3926,-1133 3926,-933 ; 4902,-930 4902,-727.17
  text "COMPONENTS MARKED 'DNP' SHOULD NOT BE POPULATED, AND MAY NOT BE IN BILL OF MATERIALS" at 1153.5,-318.5 h40
  text "ASSEMBLY VARIANT:" at 1153,-434 h40
  text ".VariantName" at 2189,-434 h40
  text "PCB VIEWED FROM TOP SIDE" at -228.5,-655.67 h40
  text "PROJECT NAME =" at 2248,-655.67 h40
  text ".PRJ_Title" at 3117.5,-655.67 h40
  text "-" at 3662,-856.49 h40
  text ".PCB_SilkRev" at 3919,-856.49 h40
  text "TEXAS INSTRUMENTS" at 4973,-856.49 h40
  text "LAYER NAME =" at -228.5,-858.49 h40
  text "ARTWORK #    =" at 2248,-858.49 h40
  text ".prj_BasePN" at 3293.5,-858.49 h40
  text ".PCB_CopperRev" at 3729.5,-858.49 h40
  text "PLOT NAME =" at -228.5,-1064.34 h40
  text ".plot_File_Name" at 577,-1064.34 h40
  text "GENERATED    :" at 3998,-1064.34 h40
  text ".Print_Date" at 4867.5,-1064.34 h40
  text ".Print_Time" at 5596.5,-1064.34 h40
M6 Assembly Bottom:
  lines w7: -292,-726.83 6310,-726.83 ; -290,-930.17 6310,-930.17 ; 1116,-930.5 1116,-727.17 ; 2134,-1133 2134,-931 ; 3845,-929 3845,-523.5 ; 4734,-1133.5 6309.5,-1133.5 6309.5,-523.5 -292,-523.5 -292,-1133.5 2305,-1133.5 6310,-1133.5 6310,-523.5
  text "COMPONENTS MARKED 'DNP' SHOULD NOT BE POPULATED, AND MAY NOT BE IN BILL OF MATERIALS" at 6102,-318 h40
  text ".VariantName" at 5058,-434 h40
  text "ASSEMBLY VARIANT:" at 6097,-434 h40
  text ".PRJ_Title" at 2900.5,-655.67 h40
  text "PROJECT NAME =" at 3770,-655.67 h40
  text "PCB VIEWED FROM BOTTOM SIDE" at 6246.5,-655.67 h40
  text "-" at 2315,-856.49 h40
  text "TEXAS INSTRUMENTS" at 1045,-858.49 h40
  text ".PCB_SilkRev" at 2084,-858.49 h40
  text ".PCB_CopperRev" at 2285,-858.49 h40
  text ".prj_BasePN" at 2724.5,-858.49 h40
  text "880" at 2908,-858.49 h40
  text "ARTWORK #    =" at 3770,-858.49 h40
  text "LAYER NAME =" at 6246.5,-858.49 h40
  text ".Print_Time" at 421.5,-1064.34 h40
  text ".Print_Date" at 1150.5,-1064.34 h40
  text "GENERATED    :" at 2020,-1064.34 h40
  text ".plot_File_Name" at 5441,-1064.34 h40
  text "PLOT NAME =" at 6246.5,-1064.34 h40
M9 Title Sheet:
  drawing of 57 lines, arcs and shapes, not listed
  text "1" at 739.84,8036.5 h70
  text "2" at 3235.5,8036.5 h70
  text "3" at 5724.84,8036.5 h70
  text "4" at 8231.51,8036.5 h70
  text "5" at 10730.5,8036.5 h70
  text "6" at 13235.5,8036.5 h70
  text "A" at -416.5,6893.5 h70
  text "A" at 14383.5,6893.5 h70
  text "B" at -416.5,4513.5 h70
  text "B" at 14383.5,4513.5 h70
  text "C" at -416.5,2138.5 h70
  text "C" at 14383.5,2138.5 h70
  text "PROJECT TITLE:" at 11343.5,277.5 h45
  text ".PRJ_Title" at 11393.5,144.17 h70
  text "FILE NAME:" at 11343.5,-23.5 h45
  text ".PCB_File_Name_No_Path" at 11393.5,-143.5 h70
  text "D" at -416.5,-231.5 h70
  text "D" at 14383.5,-231.5 h70
  text "FAB DRAWING NUMBER:" at 11343.5,-313.5 h45
  text "551" at 11393.5,-468.49 h70
  text ".PRJ_BasePN" at 11588.5,-468.49 h70
  text "-" at 11997,-468.49 h70
  text ".PCB_CopperRev" at 12070,-468.49 h70
  text ".PCB_SilkRev" at 12295,-468.49 h70
  text "Texas Instruments (TI) and/or its licensors do not warrant the accuracy or completeness of this specification" at 6374,-605.34 h45
  text "DESIGNED FOR:" at 11343.5,-623.5 h45
  text "or any information contained therein. TI and/or its licensors do not warrant that this design will meet" at 6329.01,-718 h45
  text ".PRJ_Customer" at 11393.5,-763.5 h70
  text "the specifications, will be suitable for your application or fit for any particular purpose, or will operate in" at 6329.01,-830.67 h45
  text ".Layer_Name" at 577,-858.49 h40
  text "880" at 3117.5,-858.49 h40
  text "ALTIUM DESIGNER VERSION:" at 12888.5,-923.5 h45
  text "an implementation. TI and/or its licensors do not warrant that the design is production worthy. You should" at 6329.01,-943.33 h45
  text ".print_Scale" at 11393.5,-1025.5 h70
  text "completely validate and test your design implementation to confirm the system functionality for your application." at 6374,-1056 h45
  text ".Application_BuildNumber" at 12938.5,-1056.83 h70
  text "1" at 739.84,-1263.5 h70
  text "2" at 3235.5,-1263.5 h70
  text "3" at 5724.84,-1263.5 h70
  text "4" at 8231.51,-1263.5 h70
  text "5" at 10730.5,-1263.5 h70
  text "6" at 13235.5,-1263.5 h70
M10 Fab Notes:
  drawing of 203 lines, arcs and shapes, not listed
  text "DESIGN INFORMATION" at 12381.02,6810 h40
  text "(REFER ALSO ARRAY/PANEL PROFILING INFORMATION)" at 12019.46,6648.29 h40
  text "BOARD SIZE" at 11333.46,6644 h40
  text "2800MIL" at 11795.78,6516.18 h40
  text "X" at 12301.46,6516.18 h40
  text "1840MIL" at 12532.78,6516.18 h40
  text "Number of Layers :" at 11736.46,6319 h40
  text "2" at 12831.27,6309 h40
  text "MIN. TRACK WIDTH:" at 11736.46,6180 h40
  text "8" at 12832.7,6180 h40
  text "MIL" at 12987.46,6180 h40
  text "MIN. CLEARANCE:" at 11736.46,6048 h40
  text "7.0" at 12832.7,6048 h40
  text "MIL" at 12987.46,6048 h40
  text "MIN. VIA PAD SIZE:" at 11736.46,5916 h40
  text "24" at 12802.71,5916 h40
  text "MIL" at 12987.46,5916 h40
  text "0.05mm (2MIL)" at 12431.46,5774.29 h40
  text "MINIMUM ANNULAR RING" at 11407.23,5770 h40
  text "EXTERNAL" at 13139.46,5770 h40
  text "PER" at 11607.23,5652 h40
  text "IPC-D-275 CLASS 2 LEVEL C" at 11827.23,5652 h40
  text "MIL, HOLES" at 13315.46,5539.71 h40
  text "+/-" at 12923,5539 h40
  text "+/-" at 13777,5539 h40
  text "REGISTRATION TOLERANCES:" at 11407.23,5534 h40
  text "METAL" at 12607,5534 h40
  text "5" at 13183.2,5534 h40
  text "3" at 14016.2,5534 h40
  text "MIL" at 14132.46,5534 h40
  text "MATERIAL:" at 11332.46,5324.54 h40
  text "X" at 11615,5190 h40
  text "FR-4 High Tg" at 12318.9,5184.21 h40
  text "FR-4" at 11793.46,5175.64 h40
  text "OTHER" at 13241.46,5175.64 h40
  text "X" at 11950,5030 h40
  text "62 MIL (1.6mm) +/-10%" at 12073.56,5012.92 h40
  text "THICKNESS:" at 11407.23,5008.64 h40
  text "OTHER" at 13358.46,5008.64 h40
  text "X" at 12265,4855 h40
  text "TOLERANCE:" at 11407.23,4850.64 h40
  text "ANSI IPC-6012 TYPE 3 CLASS 2" at 12433.48,4850.64 h40
  text "OTHER +/-" at 12433.46,4694.64 h40
  text "X" at 12265,4545 h40
  text "BOW & TWIST:" at 11407.23,4537.64 h40
  text "ANSI IPC-6012 TYPE 3 CLASS 2" at 12433.48,4537.64 h40
  text "OTHER +/-" at 12433.46,4379.13 h40
  text "COPPER THICKNESS (FINISHED):" at 11332.46,4243.64 h40
  text "1.4MIL (1oz)" at 12212.46,4090.92 h40
  text "2MIL (1.4oz)" at 12979.46,4090.92 h40
  text "2.8MIL (2oz)" at 13706.46,4090.92 h40
  text "OUTER:" at 11689.46,4086.64 h40
  text "X" at 13595,4080 h40
  text "1.4MIL (1oz)" at 12562.46,3933.92 h40
  text "2.8MIL (2oz)" at 13406.46,3933.92 h40
  text "INNER SIGNAL:" at 11689.46,3929.64 h40
  text "DRILLING:" at 11332.46,3790.64 h40
  text "REFERENCE:" at 11407.23,3673.64 h40
  text "X" at 12055.46,3673.64 h40
  text "AS SHOWN" at 12242.46,3673.64 h40
  text "X" at 12956.46,3673.64 h40
  text "NC_DRILL FILES" at 13093.46,3673.64 h40
  text "PTH MIN COPPER THICKNESS:" at 11407.23,3515.64 h40
  text "X" at 12757.46,3515.64 h40
  text "1MIL" at 12894.46,3515.64 h40
  text "OTHER" at 13391.46,3515.64 h40
  text "BOARD FINISH:" at 11332.46,3356.64 h40
  text "SILKSCREEN:" at 11487.68,3238.64 h40
  text "X" at 12436.46,3238.64 h40
  text "TOP" at 12562.46,3238.64 h40
  text "X" at 12946.46,3238.64 h40
  text "BOTTOM" at 13073.46,3238.64 h40
  text "SILKSCREEN COLOR:" at 11487.68,3071.64 h40
  text "X" at 12435.42,3071.64 h40
  text "WHITE" at 12562.46,3071.64 h40
  text "OTHER" at 13073.46,3071.64 h40
  text "SOLDER RESIST COLOR:" at 11487.68,2901.64 h40
  text "X" at 12055.42,2742.44 h40
  text "GREEN" at 12182.46,2742.44 h40
  text "BLUE" at 12773.46,2742.44 h40
  text "OTHER" at 13311.46,2742.44 h40
  text "IMMERSION GOLD (ENIG)" at 12393.46,2553.92 h40
  text "SURFACE FINISH:" at 11332.46,2549.64 h40
  text "Pb-FREE HASL" at 13625.75,2549.64 h40
  text "HASL" at 12750,2430 h40
  text "X" at 12209,2393 h40
  text "OTHER" at 12393.46,2392.64 h40
  text "X" at 12200,2220 h40
  text "ARRAY/PANEL:" at 11332.46,2213.64 h40
  text "CUT AND TRIM PER MECH LAYER 1" at 12393.46,2209.35 h40
  text "N.C. ROUTE" at 12393.46,2057.64 h40
  text "V. SCORE" at 13259.46,2057.64 h40
  text "CERTIFICATION:" at 11332.46,1920.64 h40
  text "MATERIALS AND WORKMANSHIP FOR ALL PCBS" at 12057.46,1920.64 h40
  text "TO MEET OR EXCEED THE REQUIREMENTS OF:" at 12057.46,1822.64 h40
  text "X" at 11683.96,1686.13 h40
  text "ANSI IPC-A-600F CLASS ->" at 11822.96,1686.13 h40
  text "X" at 13462.02,1686.13 h40
  text "2" at 13580.96,1686.14 h40
  text "1" at 13265.96,1684.64 h40
  text "3" at 13934.96,1684.64 h40
  text "X" at 11686.02,1526.64 h40
  text "UL 94V-0" at 11822.96,1526.64 h40
  text "X" at 12498.02,1526.64 h40
  text "RoHS" at 12634.96,1526.64 h40
  text "OTHER" at 13279.36,1526.64 h40
  text "PER ORDER" at 13676.42,1526.64 h40
  text "ADDITIONAL REQUIREMENTS:" at 11332.46,1385.64 h40
  text "MICROSECTION:" at 11407.23,1270.64 h40
  text "YES" at 12312.96,1270.64 h40
  text "REQUIRED" at 13174.46,1114.49 h40
  text "BARE BOARD ELEC. TEST:" at 11407.23,1111.64 h40
  text "NONE" at 12712.96,1111.64 h40
  text "PER ORDER" at 13766.46,1111.64 h40
  text "X" at 12580,1110 h40
  text "MANUFACTURER'S ID/LOGO:" at 11407.23,954.64 h40
  text "X" at 13740,955 h40
  text "RAIL" at 12872.96,950.35 h40
  text "METAL" at 13364.77,950.35 h40
  text "SILK" at 13876.46,950.35 h40
  text ".Layer_Name" at 577,-858.49 h40
  text "880" at 3117.5,-858.49 h40
M11 Gerber Information:
  lines w7: -292,-930.17 6308,-930.17 ; -292,-726.83 6310,-726.83 ; -292,-523.5 -292,-1133.5 3713,-1133.5 6310,-1133.5 6310,-523.5 -291.5,-523.5 -291.5,-1133.5 1284,-1133.5 ; 2173,-929 2173,-523.5 ; 3926,-1133 3926,-933 ; 4902,-930 4902,-727.17
  text "ALL ARTWORK VIEWED FROM TOP SIDE" at -228.5,-655.67 h40
  text "PROJECT NAME =" at 2248,-655.67 h40
  text ".PRJ_Title" at 3117.5,-655.67 h40
  text "-" at 3662,-856.49 h40
  text ".PCB_SilkRev" at 3919,-856.49 h40
  text "TEXAS INSTRUMENTS" at 4973,-856.49 h40
  text "LAYER NAME =" at -228.5,-858.49 h40
  text "ARTWORK #    =" at 2248,-858.49 h40
  text ".prj_BasePN" at 3293.5,-858.49 h40
  text ".PCB_CopperRev" at 3729.5,-858.49 h40
  text "PLOT NAME =" at -228.5,-1064.34 h40
  text ".plot_File_Name" at 577,-1064.34 h40
  text "GENERATED    :" at 3998,-1064.34 h40
  text ".Print_Date" at 4867.5,-1064.34 h40
  text ".Print_Time" at 5596.5,-1064.34 h40
M12 Stackup:
  lines w16: 5205,6613 10115,6613 ; 5205,6903.7 10115,6903.7 ; 5145,5139 ccw(c5239,5139) 5239,5045 10081,5045 ccw(c10081,5139) 10175,5139 10175,7291 ccw(c10081,7291) 10081,7385 5239,7385 ccw(c5239,7291) 5145,7291 5145,5139
  text "Layer Stack Up Detail for: PMP7883 REVB.PcbDoc" at 5205,7069.15 h104
  text "Layer" at 5205,6795.2 h67
  text "Gerber" at 6967.15,6795.2 h67
  text "Copper" at 7818.26,6795.2 h67
  text "Dielectric" at 8778.77,6795.2 h67
  text "Name" at 5205,6661.2 h67
  text "Document" at 6967.15,6661.2 h67
  text "Thickness" at 7818.26,6661.2 h67
  text "Material" at 8778.77,6661.2 h67
  text "Top Solder Mask" at 5205,6350 h94
  text "(.GTS)" at 6967.15,6350 h94
  text "Solder Resist" at 8778.77,6350 h94
  text "Top Layer" at 5205,6010 h94
  text "(.GTL)" at 6967.15,6010 h94
  text "2.8mil" at 7818.26,6010 h94
  text "FR-4" at 8778.77,5840 h94
  text "Bottom Layer" at 5205,5670 h94
  text "(.GBL)" at 6967.15,5670 h94
  text "2.8mil" at 7818.26,5670 h94
  text "Bottom Solder Mask" at 5205,5330 h94
  text "(.GBS)" at 6967.15,5330 h94
  text "Solder Resist" at 8778.77,5330 h94
  text ".Layer_Name" at 577,-858.49 h40
  text "880" at 3117.5,-858.49 h40
M13 Component Bodies Top:
  text ".Layer_Name" at 577,-858.49 h40
  text "880" at 3117.5,-858.49 h40
M14 Component Bodies Bottom:
  text ".Layer_Name" at 577,-858.49 h40
  text "880" at 3117.5,-858.49 h40
M15 Courtyards Top:
  text ".Layer_Name" at 577,-858.49 h40
  text "880" at 3117.5,-858.49 h40
M16 Courtyards Bottom:
  text ".Layer_Name" at 577,-858.49 h40
  text "880" at 3117.5,-858.49 h40
Drill Drawing:
  text ".legend" at 3175,1840 h40
  text "Drill Table" at 3175,1695 h40
  text ".Layer_Name" at 577,-858.49 h40
  text "880" at 3117.5,-858.49 h40

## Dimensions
2800,0 to 0,0 on M2 Board Dimensions
0,0 to 0,1840 on M2 Board Dimensions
